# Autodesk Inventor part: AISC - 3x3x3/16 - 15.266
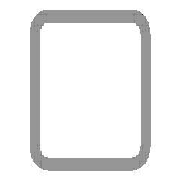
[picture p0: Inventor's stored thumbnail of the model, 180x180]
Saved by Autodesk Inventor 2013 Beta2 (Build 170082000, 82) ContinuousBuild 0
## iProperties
_CCFamilyMember: 9
_CCFamilyDisplayName: ANSI AISC (Square) - Tube
_FrameMemberDoc: Frame Member File
_Version: 15.0.0
_GetPNFromCC: 1
Created: 2011-01
Part Number: AISC - 3x3x3/16 - 15.266
Material: Steel, Mild
Description: Tube
Document SubType Name: Modeling
Standard: ANSI
Designer: Beta-8540w
Standards Organization: ANSI
Language: en-US
Size Designation: 3x3x3/16
Categories: <MemberInstance><Categories><Category DisplayName="Structural Shapes" InternalName="089c4875-fa83-4c05-b084-43b9cc11f5ed" Mnemonic="GRDR"><CategoryParameter Dis
Stock Number: 3x3x3/16
Density: 7.86 g/cm^3
IsCustomPart: 1
G_L: 15.266 in
G_W: 3.000 in
G_H: 3.000 in
+FB874C21-D68D-441B-A299-96FAE1DDA518+CUTDETAIL1: Cut
+EB3DCAF4-50CC-437C-A1F6-2B472C560A7B+CUTDETAIL2: Cut
Author: Beta-8540w
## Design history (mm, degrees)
node "Start plane"
node "End plane"
sketch "Sketch"
  geometry: L1 (-38.1, -28.575)-(-38.1, 28.575); L2 (-28.575, 38.1)-(28.575, 38.1); L3 (38.1, 28.575)-(38.1, -28.575); L4 (28.575, -38.1)-(-28.575, -38.1); L5 (-28.575, 33.337)-(28.575, 33.338); L6 (33.338, 28.575)-(33.338, -28.575); L7 (28.575, -33.337)-(-28.575, -33.338); L8 (-33.338, -28.575)-(-33.338, 28.575); L9 (0, 56.102)-(0, -56.102) reference; L10 (-56.102, 0)-(56.102, 0) reference; A1 r 9.525 centre (-28.575, -28.575) between (-38.1, -28.575) and (-28.575, -38.1); A2 r 9.525 centre (-28.575, 28.575) between (-28.575, 38.1) and (-38.1, 28.575); A3 r 9.525 centre (28.575, 28.575) between (38.1, 28.575) and (28.575, 38.1); A4 r 9.525 centre (28.575, -28.575) between (28.575, -38.1) and (38.1, -28.575); A5 r 4.763 centre (-28.575, 28.575) between (-28.575, 33.337) and (-33.338, 28.575); A6 r 4.763 centre (28.575, 28.575) between (33.338, 28.575) and (28.575, 33.338); A7 r 4.763 centre (28.575, -28.575) between (28.575, -33.337) and (33.338, -28.575); A8 r 4.763 centre (-28.575, -28.575) between (-33.338, -28.575) and (-28.575, -33.338)
  constraints: 16 end point, 16 point on circle, 8 centre point, 8 tangent, 4 parallel, 3 equal radius, 2 perpendicular, 7 other
  dimensions: "d10" = 76.2 distance between parallel lines of L2 L4 (= G_H); "d11" = 76.2 distance between parallel lines of L1 L3 (= G_W); "d12" = 4.7625 distance between parallel lines of L3 L6 (= G_T); "d15" = 38.1 distance between parallel lines of L2 L10 (= 0.5 x d10); "d16" = 38.1 distance between parallel lines of L9 L3 (= 0.5 x d11); "d17" = 9.525 radius of A1 (= G_IR)
extrude "Body" new body sketch "Sketch" stored distance "d3" = 387.75605 (= G_L); taper "d4" = 0 deg
node "Driven Length"
  sketch "Sketch3"
    geometry: L1 (0, 0)-(10, 0) reference
    constraints: 2 end point, 1 horizontal
  workplane "Work Plane3"
  sketch "Sketch4"
    geometry: L1 (-2, 31.109)-(12, 31.109) reference; L2 (-2, 418.865)-(12, 418.865) reference
    dimensions: "d19" = 387.75605 distance between parallel lines of L1 L2 (derived)
workplane "Work Plane4"
split "Split1"
workplane "Work Plane5"
split "Split2"
body "Solid1"
other parameters: "G_W" = 76.2 [user parameter; used in 1 equation term], "G_H" = 76.2 [user parameter; used in 1 equation term], "G_T" = 4.7625 [user parameter; used in 1 equation term], "G_IR" = 9.525 [user parameter; used in 1 equation term], "G_L" = 387.75605 (= d19) [user parameter; used in 1 equation term], "G_OFFSET_START" = -31.10852 [user parameter; used in 1 equation term], "G_OFFSET_END" = -31.10852 [user parameter; used in 1 equation term], "d13" = 31.10852 (= -G_OFFSET_START), "d14" = 418.86457 (= G_OFFSET_END + B_L), "B_L" = 449.97309 [user parameter; used in 1 equation term], "d18" = 90 deg
